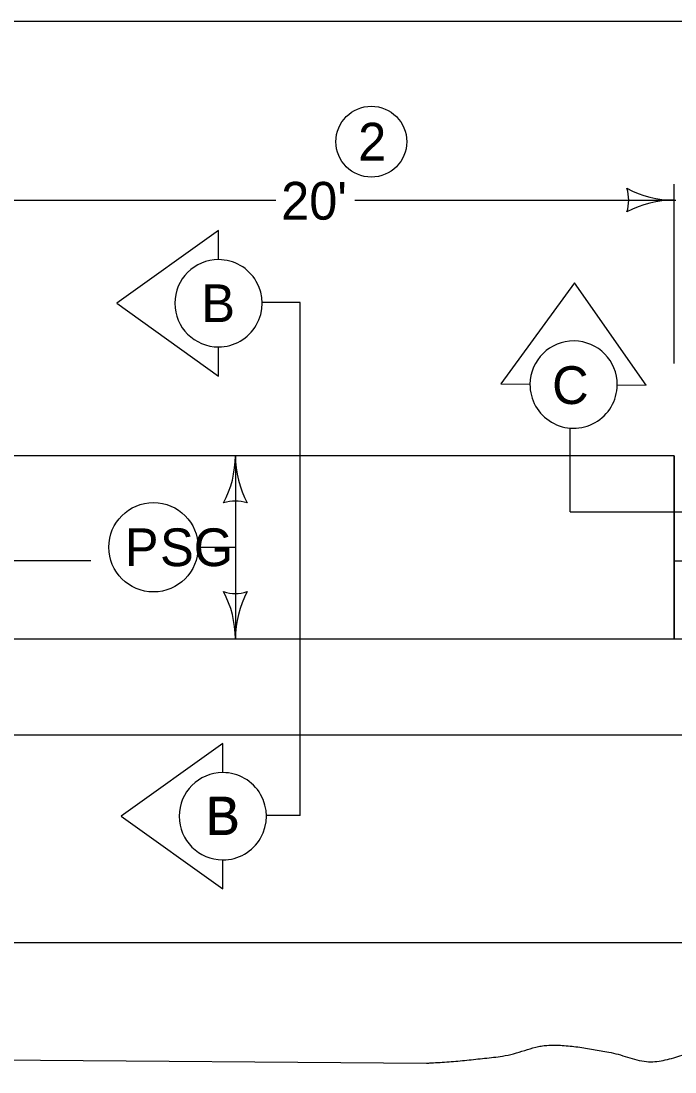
# Model space of a CAD drawing. Extents: x 6410 to 81668, y 3928 to 11667.
# Drawn here: x 7787 to 8064.2, y 9479.2 to 9924.4 of the extents above; entities that cross this region are included whole.
import ezdxf

# ---------------------------------------------------------------- set-up
doc = ezdxf.new("R2010")
doc.units = 0
for name, color, linetype in [('dsnNonPlotable', 7, 'Continuous'), ('dsnShtPlotShapeBatchPrint', 7, 'Continuous'), ('dsnStdBlockModified', 7, 'Continuous'), ('Level 10', 7, 'Continuous'), ('Level 11', 7, 'Continuous'), ('Level 7', 7, 'Continuous')]:
    doc.layers.add(name, color=color, linetype=linetype)

msp = doc.modelspace()

# ---------------------------------------------------------------- linework, layer by layer
at = {"layer": 'dsnNonPlotable'}
msp.add_line((6410.45, 9924.36), (9506.14, 9924.36), dxfattribs=at)
at = {"layer": 'dsnShtPlotShapeBatchPrint'}
for p, q in [((8063.76, 9779.31), (8063.76, 9855.32)), ((8063.76, 9779.31), (8063.76, 9855.32)), ((7759.02, 9848.49), (7895.02, 9848.49)), ((7759.02, 9848.49), (7895.02, 9848.49)), ((7928.55, 9848.49), (8064.55, 9848.49)), ((7928.55, 9848.49), (8064.55, 9848.49)), ((7877.85, 9740.23), (7877.85, 9662.65)), ((7877.85, 9740.23), (7877.85, 9662.65)), ((7862.09, 9701.44), (7877.85, 9701.44)), ((7862.09, 9701.44), (7877.85, 9701.44))]:
    msp.add_line(p, q, dxfattribs=at)
msp.add_circle((7843.16, 9701.44), 18.93, dxfattribs=at)
msp.add_circle((7843.16, 9701.44), 18.93, dxfattribs=at)
for centre, radius, start, end in [((8028.13, 9848.49), 16.42, 342.2666, 17.7333), ((8063.76, 9890.99), 42.5, 241.9275, 270), ((8028.13, 9848.49), 16.42, 342.2666, 17.7333), ((8063.76, 9890.99), 42.5, 241.9275, 270), ((8063.76, 9805.99), 42.5, 90, 118.0725), ((8063.76, 9805.99), 42.5, 90, 118.0725), ((7835.35, 9740.23), 42.5, 331.9275, 0), ((7835.35, 9740.23), 42.5, 331.9275, 0), ((7920.35, 9740.23), 42.5, 180, 208.0725), ((7920.35, 9740.23), 42.5, 180, 208.0725), ((7877.85, 9704.6), 16.42, 72.2666, 107.7334), ((7877.85, 9704.6), 16.42, 72.2666, 107.7334), ((7877.85, 9698.29), 16.42, 252.2666, 287.7333), ((7835.35, 9662.65), 42.5, 360, 28.0725), ((7877.85, 9698.29), 16.42, 252.2666, 287.7333), ((7835.35, 9662.65), 42.5, 360, 28.0725), ((7920.35, 9662.65), 42.5, 151.9275, 180), ((7920.35, 9662.65), 42.5, 151.9275, 180)]:
    msp.add_arc(centre, radius, start, end, dxfattribs=at)
at = {"layer": 'dsnStdBlockModified'}
for p, q in [((8063.76, 9740.23), (7759.02, 9740.23)), ((8063.76, 9740.23), (7759.02, 9740.23)), ((8063.76, 9740.23), (8063.76, 9662.65)), ((8063.76, 9662.65), (8063.76, 9740.23)), ((8063.76, 9695.63), (8241.65, 9695.63)), ((6605.92, 9662.65), (8253.39, 9662.65)), ((7759.02, 9662.65), (8063.76, 9662.65)), ((6627.13, 9622), (8240.92, 9622)), ((7629.61, 9485.38), (7958.81, 9482.92))]:
    msp.add_line(p, q, dxfattribs=at)
msp.add_circle((7843.16, 9701.44), 18.93, dxfattribs=at)
msp.add_spline([(7958.81, 9482.92), (7960.81, 9483.03), (7968.39, 9483.51), (7975.95, 9484.17), (7983.5, 9484.98), (7991.04, 9485.88), (7995.78, 9486.88), (8000.47, 9488.32), (8005.14, 9489.68), (8007.49, 9490.17), (8009.85, 9490.44), (8016.39, 9490.43), (8022.98, 9489.77), (8029.57, 9488.74), (8036.08, 9487.59), (8040.09, 9486.65), (8044.07, 9485.45), (8048.04, 9484.32), (8052.05, 9483.6), (8055.6, 9483.57), (8059.15, 9484.07), (8066.25, 9486), (8073.39, 9488.01), (8080.56, 9488.73), (8095.1, 9487.76), (8109.64, 9486.45), (8116.36, 9485.63), (8123.07, 9484.64), (8129.76, 9483.7), (8136.44, 9483.03), (8142.2, 9483.59), (8147.87, 9485.42), (8153.54, 9487.47), (8159.25, 9488.73), (8166.75, 9489.24), (8174.36, 9489.37), (8185.74, 9488.67), (8189.48, 9488.16), (8196.5, 9486.34), (8203.39, 9483.78), (8210.31, 9481.41), (8217.42, 9480.18), (8238.52, 9479.17)], degree=3, dxfattribs=at)
at = {"layer": 'Level 10'}
for p, q in [((7905.28, 9805.1), (7889.5, 9805.1)), ((7905.28, 9805.1), (7889.5, 9805.1)), ((7905.28, 9587.81), (7905.28, 9805.1)), ((7905.28, 9587.81), (7905.28, 9805.1)), ((8019.71, 9716.47), (8019.71, 9751.91)), ((8019.71, 9716.47), (8019.71, 9751.91)), ((8019.71, 9716.47), (8107.82, 9716.47)), ((8019.71, 9716.47), (8107.82, 9716.47)), ((7905.28, 9587.81), (7891.32, 9587.81)), ((7905.28, 9587.81), (7891.32, 9587.81))]:
    msp.add_line(p, q, dxfattribs=at)
for points in [[(7870.71, 9823.28), (7870.71, 9835.61), (7827.58, 9804.8), (7870.71, 9773.99), (7870.71, 9786.31)], [(8039.68, 9770.18), (8052, 9770.07), (8021.59, 9813.48), (7990.39, 9770.63), (8002.71, 9770.52)], [(7872.53, 9606), (7872.53, 9618.32), (7829.4, 9587.51), (7872.53, 9556.7), (7872.53, 9569.02)]]:
    msp.add_lwpolyline(points, dxfattribs=at)
for centre, start, end in [((7870.71, 9804.8), 90.0008, 269.9992), ((7870.71, 9804.8), 269.9992, 90.0008), ((8021.2, 9770.35), 359.4792, 179.4775), ((8021.2, 9770.35), 179.4775, 359.4792), ((7872.53, 9587.51), 90.0008, 269.9992), ((7872.53, 9587.51), 269.9992, 90.0008)]:
    msp.add_arc(centre, 18.49, start, end, dxfattribs=at)
at = {"layer": 'Level 11'}
for p, q in [((7816.57, 9695.63), (6784.66, 9695.63)), ((6610.53, 9534.09), (8252.57, 9534.09))]:
    msp.add_line(p, q, dxfattribs=at)
at = {"layer": 'Level 7'}
msp.add_circle((7935.48, 9873.25), 15, dxfattribs=at)

# ---------------------------------------------------------------- texts
at = {"layer": 'dsnShtPlotShapeBatchPrint'}
for s, p in [("20'", (7897.26, 9840.22)), ("20'", (7897.26, 9840.22)), ('SG', (7845.95, 9693.44)), ('SG', (7845.95, 9693.44)), ('P', (7831.03, 9693.44)), ('P', (7831.03, 9693.44))]:
    msp.add_text(s, height=16, dxfattribs=at).set_placement(p)
at = {"layer": 'Level 10'}
for s, p in [('B', (7863.44, 9796.8)), ('B', (7863.44, 9796.8)), ('C', (8012.09, 9762.12)), ('C', (8012.09, 9762.12)), ('B', (7865.26, 9579.51)), ('B', (7865.26, 9579.51)), ('B', (7865.54, 9579.81)), ('B', (7865.54, 9579.81))]:
    msp.add_text(s, height=16, dxfattribs=at).set_placement(p)
at = {"layer": 'Level 7'}
msp.add_text('2', height=16, dxfattribs=at).set_placement((7929.9, 9865.25))

doc.saveas('drawing.dxf')
